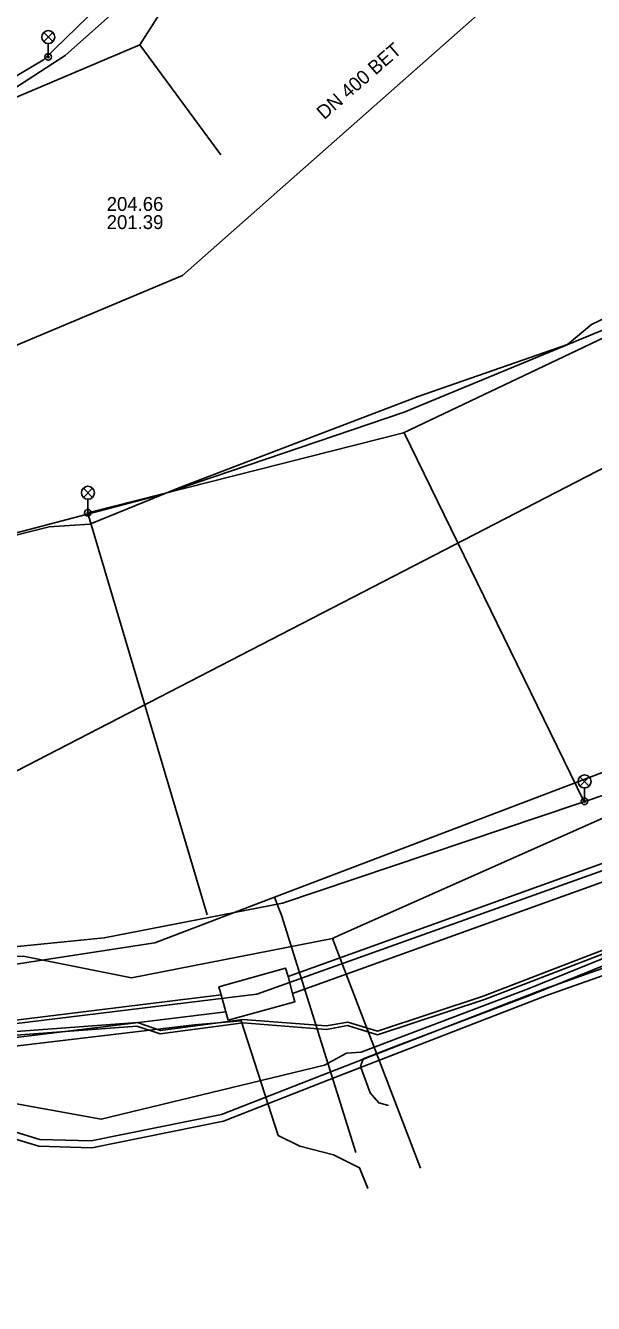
# Model space of a CAD drawing. Extents: x -596228 to -595156, y -1161235 to -1159373.
# Drawn here: x -595705.3 to -595672.5, y -1160372.3 to -1160298.5 of the extents above; entities that cross this region are included whole.
import ezdxf

# ---------------------------------------------------------------- set-up
doc = ezdxf.new("R2010")
doc.units = 0
for name, color, linetype in [('Vrstva 10', 7, 'Continuous'), ('Vrstva 12', 7, 'Continuous'), ('Vrstva 14', 7, 'Continuous'), ('Vrstva 16', 7, 'Continuous'), ('Vrstva 33', 7, 'Continuous'), ('Vrstva 42', 7, 'Continuous'), ('Vrstva 44', 7, 'Continuous'), ('Vrstva 54', 7, 'Continuous'), ('Vrstva 55', 7, 'Continuous'), ('Vrstva 58', 7, 'Continuous'), ('Vrstva 9', 7, 'Continuous')]:
    doc.layers.add(name, color=color, linetype=linetype)

msp = doc.modelspace()

# ---------------------------------------------------------------- linework, layer by layer
at = {"layer": 'Vrstva 10'}
for p, q in [((-595623.84, -1160329.51), (-595690.16, -1160353.38)), ((-595623.84, -1160329.51), (-595690.16, -1160353.38)), ((-595623.5, -1160330.45), (-595689.9, -1160354.35)), ((-595623.5, -1160330.45), (-595689.9, -1160354.35)), ((-595690.16, -1160353.38), (-595689.9, -1160354.35)), ((-595690.16, -1160353.38), (-595689.9, -1160354.35)), ((-595694.02, -1160354.44), (-595731.23, -1160359)), ((-595694.02, -1160354.44), (-595731.23, -1160359)), ((-595694.02, -1160354.44), (-595693.75, -1160355.42)), ((-595694.02, -1160354.44), (-595693.75, -1160355.42)), ((-595693.75, -1160355.42), (-595731.26, -1160360.01)), ((-595693.75, -1160355.42), (-595731.26, -1160360.01))]:
    msp.add_line(p, q, dxfattribs=at)
for points in [[(-595694.02, -1160354.44), (-595694.15, -1160353.97), (-595690.3, -1160352.9), (-595690.16, -1160353.38)], [(-595694.02, -1160354.44), (-595694.15, -1160353.97), (-595690.3, -1160352.9), (-595690.16, -1160353.38)], [(-595689.9, -1160354.35), (-595689.76, -1160354.83), (-595693.62, -1160355.9), (-595693.75, -1160355.42)], [(-595689.9, -1160354.35), (-595689.76, -1160354.83), (-595693.62, -1160355.9), (-595693.75, -1160355.42)]]:
    msp.add_lwpolyline(points, dxfattribs=at)
at = {"layer": 'Vrstva 12'}
for points in [[(-595733.28, -1160359.44), (-595691.96, -1160354.4), (-595622.73, -1160329.64), (-595621.78, -1160329.3), (-595618.62, -1160330.73), (-595554.08, -1160306.33)], [(-595685.56, -1160365.61), (-595686.03, -1160364.43), (-595687.54, -1160363.68), (-595689.47, -1160363.18), (-595690.72, -1160362.55), (-595692.86, -1160355.94), (-595695.56, -1160356.17), (-595706.92, -1160357.51), (-595714.99, -1160357.98), (-595720.77, -1160358.7), (-595728.66, -1160359.87), (-595733.06, -1160360.59)]]:
    msp.add_lwpolyline(points, dxfattribs=at)
at = {"layer": 'Vrstva 14'}
for points in [[(-595749.15, -1160356.25), (-595745.334, -1160357.016), (-595740.305, -1160357.959), (-595721.901, -1160355.127), (-595697.852, -1160351.426), (-595690.937, -1160348.796), (-595633.652, -1160327.007)], [(-595690.937, -1160348.796), (-595690.692, -1160349.441), (-595690.54, -1160349.841), (-595686.236, -1160363.549)]]:
    msp.add_lwpolyline(points, dxfattribs=at)
at = {"layer": 'Vrstva 16'}
for points in [[(-595846.15, -1160336.98), (-595838.77, -1160338.11), (-595833.73, -1160339.33), (-595822.21, -1160341.41), (-595795.62, -1160345.96), (-595752.4, -1160353.65), (-595705.45, -1160352.2), (-595699.2, -1160353.46), (-595687.59, -1160351.18), (-595687.183, -1160350.999), (-595649.82, -1160334.37), (-595637.18, -1160329.71), (-595632.58, -1160328.19), (-595631.22, -1160327.8), (-595629.94, -1160327.43), (-595628.67, -1160326.89), (-595623.45, -1160328.11), (-595616.75, -1160330.26), (-595616.2, -1160330.11), (-595541.13, -1160299.69), (-595536.93, -1160298.59)], [(-595687.59, -1160351.18), (-595683.3, -1160362.38), (-595682.51, -1160364.44)]]:
    msp.add_lwpolyline(points, dxfattribs=at)
at = {"layer": 'Vrstva 33'}
for p, q in [((-595704.265, -1160298.855), (-595703.735, -1160299.385)), ((-595704.265, -1160299.385), (-595703.735, -1160298.855)), ((-595704, -1160300.27), (-595704, -1160299.495)), ((-595701.975, -1160325.175), (-595701.445, -1160325.705)), ((-595701.975, -1160325.705), (-595701.445, -1160325.175)), ((-595701.71, -1160326.59), (-595701.71, -1160325.815)), ((-595673.305, -1160341.845), (-595672.775, -1160342.375)), ((-595673.305, -1160342.375), (-595672.775, -1160341.845)), ((-595673.04, -1160343.26), (-595673.04, -1160342.485))]:
    msp.add_line(p, q, dxfattribs=at)
for centre, radius in [((-595704, -1160299.12), 0.375), ((-595704, -1160300.27), 0.19), ((-595704, -1160300.27), 0.05), ((-595701.71, -1160325.44), 0.375), ((-595701.71, -1160326.59), 0.19), ((-595701.71, -1160326.59), 0.05), ((-595673.04, -1160342.11), 0.375), ((-595673.04, -1160343.26), 0.19), ((-595673.04, -1160343.26), 0.05)]:
    msp.add_circle(centre, radius, dxfattribs=at)
at = {"layer": 'Vrstva 42'}
for points in [[(-595847.13, -1160313.44), (-595833.42, -1160315.69), (-595818.81, -1160318.02), (-595804.19, -1160320.42), (-595787.39, -1160322.98), (-595780.95, -1160322.96), (-595774.21, -1160321.77), (-595762.67, -1160319.43), (-595752.552, -1160316.857), (-595741.43, -1160313.41), (-595738.39, -1160315.27), (-595735.13, -1160315.87), (-595731.62, -1160314.9), (-595724.29, -1160311.87), (-595722.868, -1160311.197), (-595714.82, -1160307.83), (-595703.02, -1160300.19), (-595693.78, -1160291.95), (-595681.58, -1160277.83), (-595677.955, -1160273.423), (-595678.45, -1160273.05)], [(-595847.13, -1160313.44), (-595833.42, -1160315.69), (-595818.81, -1160318.02), (-595804.19, -1160320.42), (-595787.39, -1160322.98), (-595780.95, -1160322.96), (-595774.21, -1160321.77), (-595762.67, -1160319.43), (-595752.552, -1160316.857), (-595741.43, -1160313.41), (-595738.39, -1160315.27), (-595735.13, -1160315.87), (-595731.62, -1160314.9), (-595724.29, -1160311.87), (-595722.868, -1160311.197), (-595714.82, -1160307.83), (-595703.02, -1160300.19), (-595693.78, -1160291.95), (-595681.58, -1160277.83), (-595677.955, -1160273.423), (-595678.45, -1160273.05)], [(-595678.45, -1160273.05), (-595677.955, -1160273.423), (-595681.58, -1160277.83), (-595693.78, -1160291.95), (-595703.02, -1160300.19), (-595714.82, -1160307.83), (-595722.868, -1160311.197), (-595724.29, -1160311.87), (-595731.62, -1160314.9), (-595735.13, -1160315.87), (-595738.39, -1160315.27), (-595741.43, -1160313.41), (-595752.552, -1160316.857), (-595762.67, -1160319.43), (-595774.21, -1160321.77), (-595780.95, -1160322.96), (-595787.39, -1160322.98), (-595804.19, -1160320.42), (-595818.81, -1160318.02), (-595833.42, -1160315.69), (-595847.13, -1160313.44)], [(-595847.13, -1160313.44), (-595833.42, -1160315.69), (-595818.81, -1160318.02), (-595804.19, -1160320.42), (-595787.39, -1160322.98), (-595780.95, -1160322.96), (-595774.21, -1160321.77), (-595762.67, -1160319.43), (-595752.552, -1160316.857), (-595741.43, -1160313.41), (-595738.39, -1160315.27), (-595735.13, -1160315.87), (-595731.62, -1160314.9), (-595724.29, -1160311.87), (-595722.868, -1160311.197), (-595714.82, -1160307.83), (-595703.02, -1160300.19), (-595693.78, -1160291.95), (-595681.58, -1160277.83), (-595677.955, -1160273.423)], [(-595847.13, -1160313.44), (-595833.42, -1160315.69), (-595818.81, -1160318.02), (-595804.19, -1160320.42), (-595787.39, -1160322.98), (-595780.95, -1160322.96), (-595774.21, -1160321.77), (-595762.67, -1160319.43), (-595752.552, -1160316.857), (-595741.43, -1160313.41), (-595738.39, -1160315.27), (-595735.13, -1160315.87), (-595731.62, -1160314.9), (-595724.29, -1160311.87), (-595722.868, -1160311.197), (-595714.82, -1160307.83), (-595703.02, -1160300.19), (-595693.78, -1160291.95), (-595681.58, -1160277.83), (-595677.955, -1160273.423)], [(-595847.13, -1160313.44), (-595833.42, -1160315.69), (-595818.81, -1160318.02), (-595804.19, -1160320.42), (-595787.39, -1160322.98), (-595780.95, -1160322.96), (-595774.21, -1160321.77), (-595762.67, -1160319.43), (-595752.552, -1160316.857), (-595741.43, -1160313.41), (-595738.39, -1160315.27), (-595735.13, -1160315.87), (-595731.62, -1160314.9), (-595724.29, -1160311.87), (-595722.868, -1160311.197), (-595714.82, -1160307.83), (-595703.02, -1160300.19), (-595693.78, -1160291.95), (-595681.58, -1160277.83), (-595677.955, -1160273.423)], [(-595847.13, -1160313.44), (-595833.42, -1160315.69), (-595818.81, -1160318.02), (-595804.19, -1160320.42), (-595787.39, -1160322.98), (-595780.95, -1160322.96), (-595774.21, -1160321.77), (-595762.67, -1160319.43), (-595752.552, -1160316.857), (-595741.43, -1160313.41), (-595738.39, -1160315.27), (-595735.13, -1160315.87), (-595731.62, -1160314.9), (-595724.29, -1160311.87), (-595722.868, -1160311.197), (-595714.82, -1160307.83), (-595703.02, -1160300.19), (-595693.78, -1160291.95), (-595681.58, -1160277.83), (-595677.955, -1160273.423)], [(-595661.84, -1160310.55), (-595672.63, -1160315.73), (-595674.02, -1160316.87), (-595682.65, -1160319.88), (-595696.41, -1160325.14), (-595701.61, -1160327.25), (-595703.94, -1160327.4), (-595716.82, -1160330.64), (-595730.14, -1160332.55), (-595739.66, -1160333.13), (-595739.784, -1160331.942)], [(-595661.84, -1160310.55), (-595672.63, -1160315.73), (-595674.02, -1160316.87), (-595682.65, -1160319.88), (-595696.41, -1160325.14), (-595701.61, -1160327.25), (-595703.94, -1160327.4), (-595716.82, -1160330.64), (-595730.14, -1160332.55), (-595739.66, -1160333.13), (-595739.784, -1160331.942)], [(-595661.84, -1160310.55), (-595672.63, -1160315.73), (-595674.02, -1160316.87), (-595682.65, -1160319.88), (-595696.41, -1160325.14), (-595701.61, -1160327.25), (-595703.94, -1160327.4), (-595716.82, -1160330.64), (-595730.14, -1160332.55), (-595739.66, -1160333.13), (-595739.784, -1160331.942)], [(-595661.84, -1160310.55), (-595672.63, -1160315.73), (-595674.02, -1160316.87), (-595682.65, -1160319.88), (-595696.41, -1160325.14), (-595701.61, -1160327.25), (-595703.94, -1160327.4), (-595716.82, -1160330.64), (-595730.14, -1160332.55), (-595739.66, -1160333.13), (-595739.784, -1160331.942)], [(-595684.368, -1160360.824), (-595684.917, -1160360.681), (-595685.413, -1160360.091), (-595685.972, -1160358.576), (-595685.818, -1160358.132), (-595683.778, -1160357.346), (-595676.157, -1160354.454), (-595668.12, -1160351.202), (-595661.252, -1160348.583), (-595657.317, -1160347.241), (-595654.155, -1160345.935), (-595650.379, -1160344.379), (-595642.25, -1160341.127), (-595634.857, -1160338.343), (-595634.455, -1160338.192), (-595634.099, -1160338.102), (-595633.626, -1160337.982), (-595633.34, -1160338.061), (-595633.301, -1160338.072), (-595633.034, -1160338.246), (-595632.057, -1160338.881), (-595631.753, -1160339.163), (-595631.429, -1160340.113)], [(-595719.587, -1160365.396), (-595719.841, -1160363.392), (-595719.542, -1160359.988), (-595719.363, -1160357.944), (-595715.182, -1160357.251), (-595698.857, -1160356.039), (-595697.53, -1160356.488), (-595692.763, -1160355.859), (-595687.955, -1160356.229), (-595686.714, -1160356.007), (-595685.001, -1160356.535), (-595678.894, -1160354.516), (-595665.947, -1160349.527)], [(-595665.873, -1160349.713), (-595678.826, -1160354.704), (-595684.999, -1160356.745), (-595686.726, -1160356.213), (-595687.945, -1160356.431), (-595692.757, -1160356.061), (-595697.55, -1160356.692), (-595698.883, -1160356.241), (-595715.158, -1160357.449), (-595719.177, -1160358.116), (-595719.33, -1160359.866), (-595719.639, -1160363.388), (-595719.399, -1160365.292)], [(-595712.865, -1160359.458), (-595700.941, -1160361.622), (-595692.263, -1160359.508), (-595688.045, -1160358.497), (-595686.777, -1160357.803), (-595685.944, -1160357.751), (-595683.92, -1160356.972), (-595676.303, -1160354.082), (-595668.266, -1160350.83)]]:
    msp.add_lwpolyline(points, dxfattribs=at)
at = {"layer": 'Vrstva 44'}
for points in [[(-595717.364, -1160360.106), (-595716.77, -1160359.938), (-595712.271, -1160360.888), (-595708.136, -1160362.092), (-595704.554, -1160363.181), (-595701.491, -1160363.274), (-595693.888, -1160361.725), (-595687.262, -1160359.141), (-595675.243, -1160354.482), (-595665.747, -1160351.12), (-595656.455, -1160347.611), (-595651.761, -1160345.734), (-595642.65, -1160342.268), (-595626.862, -1160337.683), (-595610.795, -1160332.384), (-595601.354, -1160328.949), (-595593.41, -1160326.668), (-595585.132, -1160323.221), (-595576.808, -1160319.609), (-595564.888, -1160314.602), (-595558.278, -1160311.976), (-595541.589, -1160305.764), (-595540.697, -1160305.102), (-595540.254, -1160304.773)], [(-595717.89, -1160359.792), (-595716.784, -1160359.526), (-595712.174, -1160360.5), (-595708.022, -1160361.709), (-595704.489, -1160362.783), (-595701.525, -1160362.873), (-595694.001, -1160361.34), (-595687.407, -1160358.768), (-595675.382, -1160354.107), (-595665.884, -1160350.744), (-595656.6, -1160347.238), (-595651.906, -1160345.361), (-595642.777, -1160341.888), (-595626.98, -1160337.301), (-595610.926, -1160332.006), (-595601.478, -1160328.568), (-595593.543, -1160326.29), (-595585.289, -1160322.853), (-595576.965, -1160319.241), (-595565.039, -1160314.232)]]:
    msp.add_lwpolyline(points, dxfattribs=at)
at = {"layer": 'Vrstva 54'}
for p, q in [((-595698.72, -1160299.57), (-595690.45, -1160286.59)), ((-595716, -1160306.91), (-595698.72, -1160299.57)), ((-595698.72, -1160299.57), (-595694.03, -1160305.93)), ((-595673.084, -1160343.252), (-595683.455, -1160321.978)), ((-595694.819, -1160349.806), (-595701.733, -1160326.555))]:
    msp.add_line(p, q, dxfattribs=at)
msp.add_lwpolyline([(-595701.714, -1160326.591), (-595683.484, -1160321.975), (-595661.488, -1160311.527)], dxfattribs=at)
at = {"layer": 'Vrstva 55'}
for points in [[(-595753.08, -1160321.36), (-595752.925, -1160321.596), (-595735.26, -1160315.97), (-595722.68, -1160311.35), (-595704.28, -1160300.44), (-595687.656, -1160284.282), (-595687.61, -1160283.8)], [(-595549.591, -1160289.23), (-595553.77, -1160289.9), (-595560.32, -1160292.33), (-595603.64, -1160310.74), (-595629.87, -1160322.68), (-595651.581, -1160331.852), (-595671.361, -1160342.72), (-595690.48, -1160349.14), (-595700.77, -1160351.15), (-595713.32, -1160352.4), (-595737.16, -1160354.91), (-595741.43, -1160359.43), (-595737.66, -1160362.94), (-595735.46, -1160369.37), (-595740.08, -1160372.02)], [(-595641.433, -1160297.27), (-595641.28, -1160297.69), (-595642.79, -1160301.95), (-595645.8, -1160305.22), (-595683.45, -1160320.78), (-595697.51, -1160325.55), (-595715.58, -1160330.31), (-595736.829, -1160332.482), (-595742.491, -1160332.8), (-595749.21, -1160333.08), (-595745.95, -1160355.16), (-595741.43, -1160359.18), (-595737.41, -1160363.19), (-595735.15, -1160369.47), (-595738.78, -1160371.82), (-595739.832, -1160372.258)]]:
    msp.add_lwpolyline(points, dxfattribs=at)
at = {"layer": 'Vrstva 58'}
msp.add_lwpolyline([(-595685.56, -1160365.62), (-595686.03, -1160364.43), (-595687.54, -1160363.68), (-595689.47, -1160363.18), (-595690.72, -1160362.55), (-595692.86, -1160355.94), (-595695.56, -1160356.17), (-595706.92, -1160357.51), (-595714.99, -1160357.98), (-595720.77, -1160358.7), (-595728.66, -1160359.87), (-595733.06, -1160360.59)], dxfattribs=at)
at = {"layer": 'Vrstva 9'}
for p, q in [((-595696.26, -1160312.9), (-595736.02, -1160329.55)), ((-595671.75, -1160323.9), (-595708.84, -1160343.06))]:
    msp.add_line(p, q, dxfattribs=at)
msp.add_lwpolyline([(-595658.76, -1160279.74), (-595660.079, -1160280.905), (-595696.26, -1160312.9)], dxfattribs=at)

# ---------------------------------------------------------------- texts
at = {"layer": 'Vrstva 12'}
msp.add_text('DN 400 BET', height=0.8, rotation=41, dxfattribs=at).set_placement((-595688.076, -1160303.928))
for s, p in [('204.66', (-595700.628, -1160309.16)), ('201.39', (-595700.628, -1160310.21))]:
    msp.add_text(s, height=0.8, dxfattribs=at).set_placement(p)

doc.saveas('drawing.dxf')
